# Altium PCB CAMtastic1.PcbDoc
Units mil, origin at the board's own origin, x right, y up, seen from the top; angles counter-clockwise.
Board outline 3395.54 x 1744.22 mil, 2 copper layers (Top Layer, Bottom Layer); 0 components, 61 nets, 284 pads, 0 vias.
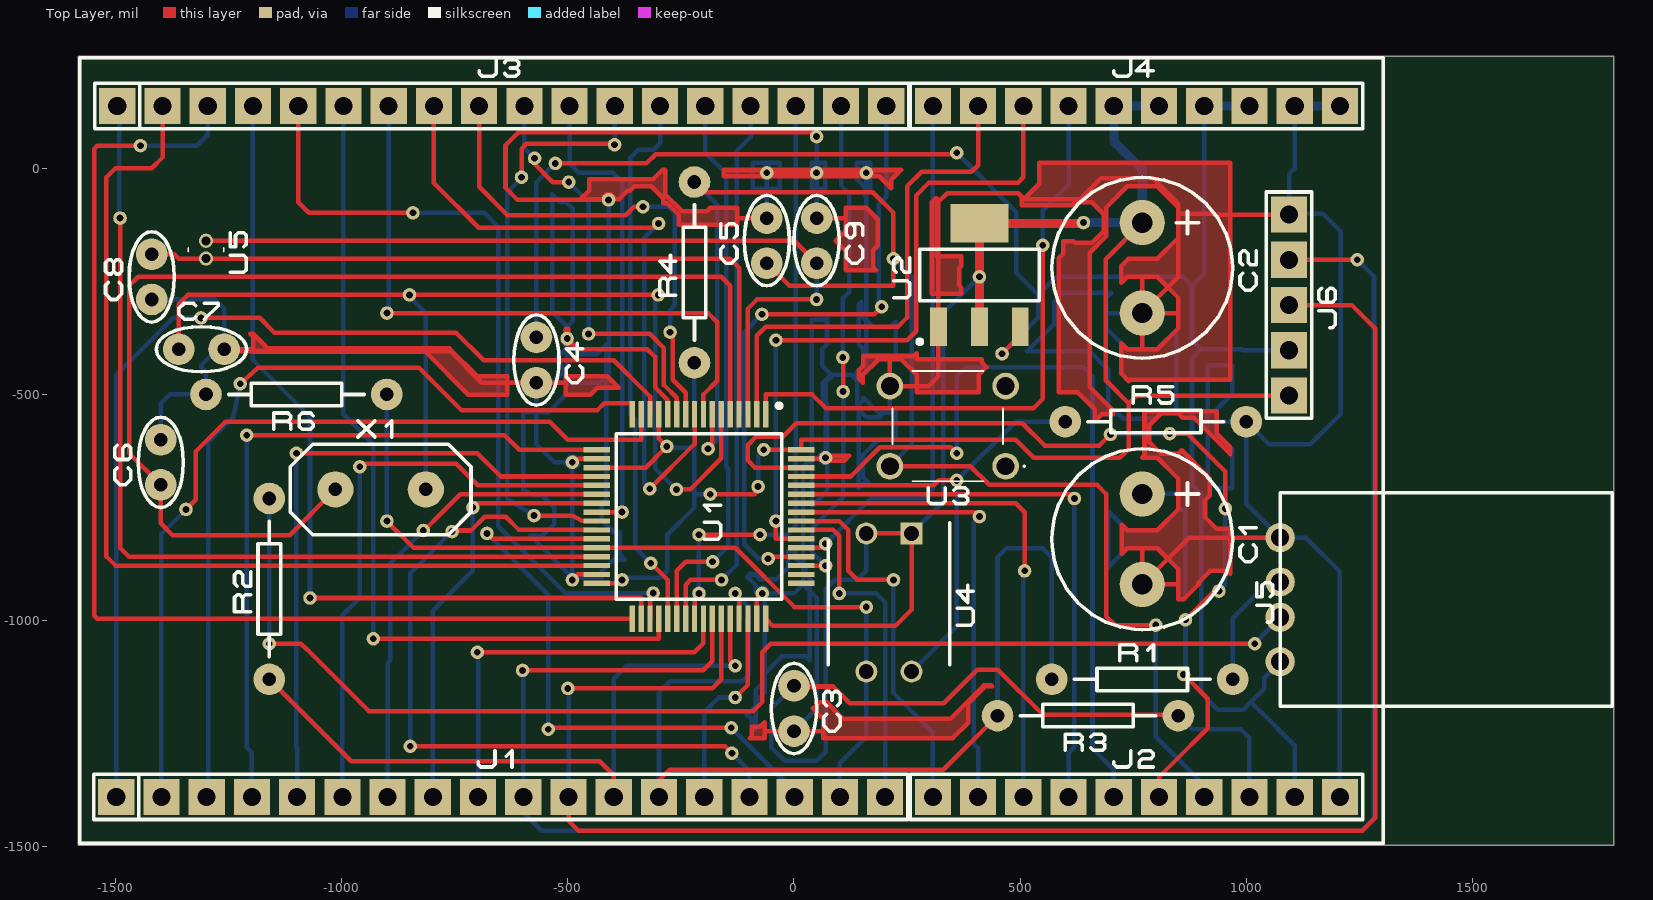
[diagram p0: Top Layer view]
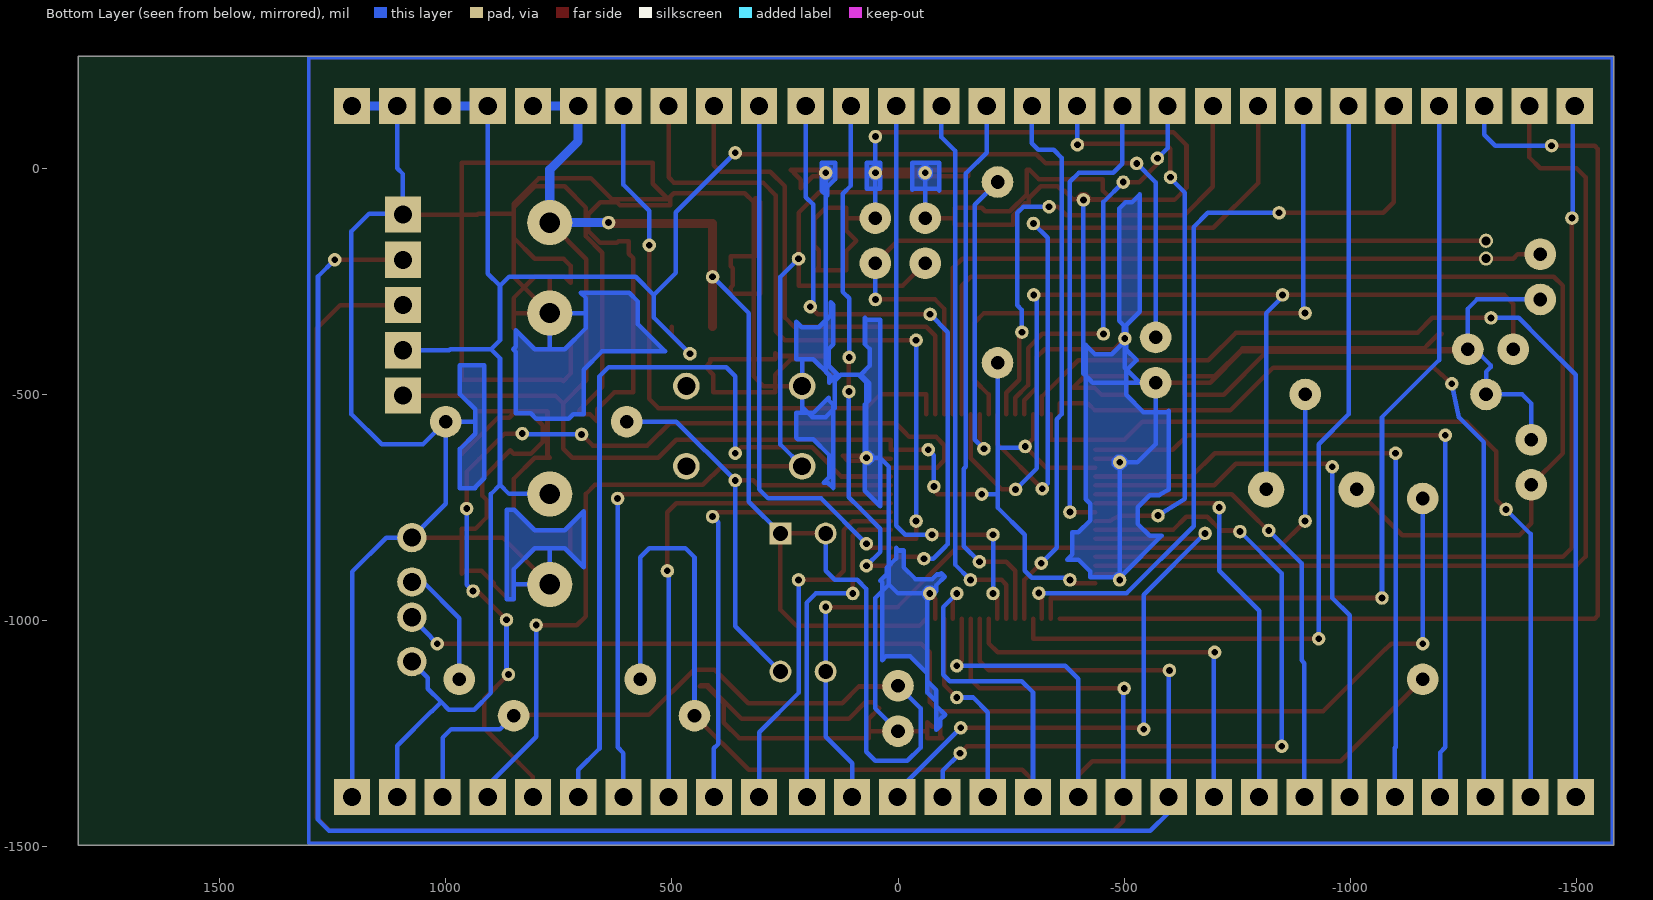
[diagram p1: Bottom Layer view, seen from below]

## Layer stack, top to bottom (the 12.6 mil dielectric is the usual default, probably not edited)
Top Solder: solder mask 0.4, Solder Resist, Dk 3.5
Top Layer: signal copper 1.4
Dielectric 1: dielectric 12.6, FR-4, Dk 4.8
Bottom Layer: signal copper 1.4
Bottom Solder: solder mask 0.4, Solder Resist, Dk 3.5

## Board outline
-1582.74,-1496.13 1812.8,-1496.13 1812.8,248.09 -1582.74,248.09

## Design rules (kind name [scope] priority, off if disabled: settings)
Clearance [All] p1: gap=10 ignorepadtopadclearanceinfootprint=FALSE except(0: Arc-Hole Track-Hole SMDPad-Hole THPad-Hole Via-Hole Fill-Hole Poly-Hole Region-Hole Text-Hole)
PolygonConnect CAM_PolygonConnect_$Net65 [InNet('$Net65')] p1: connectstyle=Direct reliefconductorwidth=10 reliefentries=4 polygonreliefangle="90 Angle" airgapwidth=10
PolygonConnect [All] p2: connectstyle=Relief reliefconductorwidth=10 reliefentries=4 polygonreliefangle="90 Angle" airgapwidth=10
RoutingVias [All] p1: holewidth=28 width=50 viastyle="Through Hole" minholewidth=28 minwidth=50 maxholewidth=28 maxwidth=50
SolderMaskExpansion [All] p1: expansion=4
Width [All] p1: maxlimit=10 minlimit=10 preferedwidth=10
30 further rules are at their usual default settings.

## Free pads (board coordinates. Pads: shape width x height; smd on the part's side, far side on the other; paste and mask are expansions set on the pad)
  rect 80x80 hole 40: 1(-1498.42,-1389.76) 1(-1496.06,137.8) 1(-1398.42,-1389.76) 1(-1396.06,137.8) 1(-1298.42,-1389.76) 1(-1296.06,137.8) 1(-1198.42,-1389.76) 1(-1196.06,137.8) 1(-1098.42,-1389.76) 1(-1096.06,137.8) 1(-998.42,-1389.76) 1(-996.06,137.8) 1(-898.42,-1389.76) 1(-896.06,137.8) 1(-798.42,-1389.76) 1(-796.06,137.8) 1(-698.42,-1389.76) 1(-696.06,137.8) 1(-598.42,-1389.76) 1(-596.06,137.8) 1(-498.42,-1389.76) 1(-496.06,137.8) 1(-398.42,-1389.76) 1(-396.06,137.8) 1(-298.42,-1389.76) 1(-296.06,137.8) 1(-198.42,-1389.76) 1(-196.06,137.8) 1(-98.42,-1389.76) 1(-96.06,137.8) 1(1.58,-1389.76) 1(3.94,137.8) 1(101.58,-1389.76) 1(103.94,137.8) 1(201.58,-1389.76) 1(203.94,137.8) 1(307.09,-1389.76) 1(307.09,137.8) 1(407.09,-1389.76) 1(407.09,137.8) 1(507.09,-1389.76) 1(507.09,137.8) 1(607.09,-1389.76) 1(607.09,137.8) 1(707.09,-1389.76) 1(707.09,137.8) 1(807.09,-1389.76) 1(807.09,137.8) 1(907.09,-1389.76) 1(907.09,137.8) 1(1007.09,-1389.76) 1(1007.09,137.8) 1(1094.49,-502.36) 1(1094.49,-402.36) 1(1094.49,-302.36) 1(1094.49,-202.36) 1(1094.49,-102.36) 1(1107.09,-1389.76) 1(1107.09,137.8) 1(1207.09,-1389.76) 1(1207.09,137.8)
  round 30 hole 15: 1(-1490,-110) 1(-1444.88,50) 1(-1344.21,-754.21) 1(-1311.02,-330.71) 1(-1224.41,-476.38) 1(-1210,-590) 1(-1160,-1051.18) 1(-1100,-630) 1(-1070,-950) 1(-960,-660) 1(-930,-1040) 1(-900,-780) 1(-900,-320) 1(-850,-280) 1(-848.44,-1277.96) 1(-842.52,-98.42) 1(-819.57,-800.76) 1(-755.91,-803.15) 1(-710,-750) 1(-700,-1070) 1(-678.82,-807.13) 1(-602.36,-19.69) 1(-600,-1110) 1(-574.8,-767.72) 1(-573.44,22.14) 1(-543.31,-1240.16) 1(-527.56,10.79) 1(-501.47,-376.47) 1(-500,-1150) 1(-497.9,-30.59) 1(-490,-910) 1(-490,-650) 1(-454.12,-366.12) 1(-410,-70) 1(-396.53,52.07) 1(-380,-910) 1(-380,-760) 1(-334.03,-84.94) 1(-318.9,-708.66) 1(-316.52,-873.02) 1(-311.3,-939.06) 1(-300,-280) 1(-299.21,-122.05) 1(-281.09,-615) 1(-273.89,-362.31) 1(-260,-710) 1(-210,-940) 1(-210,-810) 1(-190,-620) 1(-185.04,-720.47) 1(-180,-870) 1(-160,-910) 1(-138.64,-1237.06) 1(-137.2,-1293.16) 1(-130,-1170) 1(-130,-1100) 1(-130,-940) 1(-79.29,-703.77) 1(-74.8,-810) 1(-70.87,-322.83) 1(-70,-940) 1(-66.93,-622.05) 1(-60,-10) 1(-57.26,-863.06) 1(-40,-780) 1(-40,-380) 1(50,-290) 1(50,-10) 1(50,70) 1(69.95,-878.75) 1(70,-830) 1(70,-640) 1(100,-940) 1(108.03,-418.08) 1(108.68,-493.6) 1(160,-970) 1(160,-10) 1(193.89,-306.21) 1(220,-910) 1(220,-200) 1(359.87,34.19) 1(360,-690) 1(360,-630) 1(410,-770) 1(410,-240) 1(460,-410) 1(510,-890) 1(550,-170) 1(620,-730) 1(640,-120) 1(699.63,-588.44) 1(800,-1010) 1(830.71,-586.61) 1(861.52,-1119.17) 1(865.62,-998.27) 1(939.39,-934.75) 1(953.73,-752.37) 1(1018.82,-1051.18) 1(1245.33,-202.06)
  round 70 hole 30: 1(-1420,-290) 1(-1420,-190) 1(-1400,-700) 1(-1400,-600) 1(-1360,-400) 1(-1300,-500) 1(-1260,-400) 1(-1160,-1130) 1(-1160,-730) 1(-900,-500) 1(-569.37,-473.94) 1(-569.37,-373.94) 1(-220,-430.31) 1(-220,-30.31) 1(-60,-210) 1(-60,-110) 1(0,-1244.25) 1(0,-1144.25) 1(50,-210) 1(50,-110) 1(450,-1210) 1(570,-1130) 1(600,-560) 1(850,-1210) 1(970,-1130) 1(1000,-560)
  round 31.5 hole 20.1: 1(-1300,-199.69) 1(-1300,-160.31)
  round 80 hole 30: 1(-1013.94,-710) 1(-813.94,-710)
  rect 58.27x11.81 smd: 1(-435.98,-917.64) 1(-435.98,-897.95) 1(-435.98,-878.27) 1(-435.98,-858.58) 1(-435.98,-838.9) 1(-435.98,-819.21) 1(-435.98,-799.53) 1(-435.98,-779.84) 1(-435.98,-760.16) 1(-435.98,-740.47) 1(-435.98,-720.79) 1(-435.98,-701.1) 1(-435.98,-681.42) 1(-435.98,-661.73) 1(-435.98,-642.05) 1(-435.98,-622.36) 1(15.98,-917.64) 1(15.98,-897.95) 1(15.98,-878.27) 1(15.98,-858.58) 1(15.98,-838.9) 1(15.98,-819.21) 1(15.98,-799.53) 1(15.98,-779.84) 1(15.98,-760.16) 1(15.98,-740.47) 1(15.98,-720.79) 1(15.98,-701.1) 1(15.98,-681.42) 1(15.98,-661.73) 1(15.98,-642.05) 1(15.98,-622.36)
  rect 11.81x58.27 smd: 1(-357.64,-995.98) 1(-357.64,-544.02) 1(-337.95,-995.98) 1(-337.95,-544.02) 1(-318.27,-995.98) 1(-318.27,-544.02) 1(-298.58,-995.98) 1(-298.58,-544.02) 1(-278.9,-995.98) 1(-278.9,-544.02) 1(-259.21,-995.98) 1(-259.21,-544.02) 1(-239.53,-995.98) 1(-239.53,-544.02) 1(-219.84,-995.98) 1(-219.84,-544.02) 1(-200.16,-995.98) 1(-200.16,-544.02) 1(-180.47,-995.98) 1(-180.47,-544.02) 1(-160.79,-995.98) 1(-160.79,-544.02) 1(-141.1,-995.98) 1(-141.1,-544.02) 1(-121.42,-995.98) 1(-121.42,-544.02) 1(-101.73,-995.98) 1(-101.73,-544.02) 1(-82.05,-995.98) 1(-82.05,-544.02) 1(-62.36,-995.98) 1(-62.36,-544.02)
  round 48.42 hole 32.7: 1(160,-1112.76) 1(160,-807.24) 1(260,-1112.76)
  round 59.05 hole 39.4: 1(212.05,-658.58) 1(212.05,-481.42) 1(467.95,-658.58) 1(467.95,-481.42)
  rect 48.42x48.42 hole 32.7: 1(260,-807.24)
  round 10 smd far side: 1(260,-807.24) 1(1074.8,-1090.55) 1(1074.8,-992.55) 1(1074.8,-914.55) 1(1074.8,-816.55)
  round 10 smd: 1(260,-807.24) 1(1074.8,-1090.55) 1(1074.8,-992.55) 1(1074.8,-914.55) 1(1074.8,-816.55)
  rect 37x85 smd: 1(319.45,-350) 1(410,-350) 1(500.55,-350)
  rect 128x85 smd: 1(410,-121.65)
  round 100 hole 45: 1(770,-920) 1(770,-720) 1(770,-320) 1(770,-120)
  round 65 hole 40: 1(1074.8,-1090.55) 1(1074.8,-992.55) 1(1074.8,-914.55) 1(1074.8,-816.55)

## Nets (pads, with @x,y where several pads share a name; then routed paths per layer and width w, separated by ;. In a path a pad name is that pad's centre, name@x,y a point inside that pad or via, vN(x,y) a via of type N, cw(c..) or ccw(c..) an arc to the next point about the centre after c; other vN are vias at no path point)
$Net0: pad.1@50,-210 pad.1@50,-290 pad.1@-101.73,-544.02 pad.1@-1300,-160.31 | length 1844.6
  Top Layer w10: pad.1@-1300,-160.31 0.32,-160.31 pad.1@50,-210 ; pad.1@-101.73,-544.02 -101.73,-310 -81.73,-290 pad.1@50,-290
  Bottom Layer w10: pad.1@50,-290 pad.1@50,-210
$Net2: pad.1@212.05,-658.58 pad.1@220,-200 pad.1@800,-1010 pad.1@907.09,-1389.76 pad.1@-60,-210 pad.1@-180.47,-544.02 pad.1@-190,-620 pad.1@-220,-30.31 | length 3439.9
  Top Layer w10: pad.1@-220,-30.31 -197.74,-52.58 174.13,-52.58 220,-98.45 220,-200 220,-260 -10,-260 pad.1@-60,-210 ; pad.1@-190,-620 -180.47,-610.47 pad.1@-180.47,-544.02 ; pad.1@212.05,-658.58 390,-658.58 431.42,-700 670,-700 690,-720 690,-990 710,-1010 pad.1@800,-1010
  Bottom Layer w10: pad.1@-220,-30.31 -170,-80.31 -170,-600 pad.1@-190,-620 ; pad.1@212.05,-658.58 260,-610.63 260,-240 pad.1@220,-200 ; pad.1@800,-1010 800,-1256.69 907.09,-1363.78 pad.1@907.09,-1389.76
$Net3: pad.1@-200.16,-544.02 pad.1@-896.06,137.8 pad.1@-900,-320 | length 1414.2
  Top Layer w10: pad.1@-900,-320 -190,-320 -170,-340 -170,-469.84 -200.16,-500 pad.1@-200.16,-544.02
  Bottom Layer w10: pad.1@-900,-320 -896.06,-316.06 pad.1@-896.06,137.8
$Net4: pad.1@0,-1144.25 pad.1@15.98,-622.36 pad.1@160,-807.24 pad.1@260,-807.24 pad.1@410,-121.65 pad.1@410,-240 pad.1@410,-350 pad.1@640,-120 pad.1@707.09,137.8 pad.1@770,-120 pad.1@807.09,137.8 pad.1@850,-1210 pad.1@1007.09,-1389.76 pad.1@1094.49,-502.36 pad.1@-62.36,-995.98 pad.1@-66.93,-622.05 pad.1@-79.29,-703.77 pad.1@-185.04,-720.47 pad.1@-220,-430.31 pad.1@-281.09,-615 pad.1@-298.58,-544.02 pad.1@-380,-910 pad.1@-435.98,-661.73 pad.1@-435.98,-917.64 | length 7338.7
  Top Layer w10: pad.1@-435.98,-917.64 -387.64,-917.64 pad.1@-380,-910 ; pad.1@-435.98,-661.73 -327.82,-661.73 -281.09,-615 -298.58,-597.5 ; pad.1@-185.04,-720.47 -86.61,-720.47 pad.1@-79.29,-703.77 ; pad.1@-66.93,-622.05 15.67,-622.05 15.98,-622.36 15.98,-600 490,-600 530,-640 720,-640 740,-620 740,-520 ; pad.1@-62.36,-995.98 -46.54,-1011.81 224.17,-1011.81 260,-975.98 260,-807.24 200,-807.24 pad.1@160,-807.24 ; pad.1@0,-1144.25 1.42,-1145.67 86.61,-1145.67 123.37,-1182.42 331.16,-1182.42 405.23,-1108.35 450.87,-1108.35 551.18,-1208.66 850,-1208.66 pad.1@850,-1210 ; pad.1@770,-120 688.98,-201.02 688.98,-468.98 740,-520 ; pad.1@1094.49,-502.36 757.64,-502.36 740,-520 ; -298.58,-597.5 -298.58,-573.15 ; -298.58,-597.5 -298.58,-573.15 ; -298.58,-573.15 -298.58,-544.02 -298.58,-573.15
  Top Layer w20: pad.1@410,-350 410,-280 410,-240 410,-121.65 638.35,-121.65 pad.1@640,-120
  Bottom Layer w10: pad.1@-380,-910 -375.51,-905.51 -295.51,-905.51 -280,-890 -280,-810 -220,-750 -220,-720.47 ; pad.1@-281.09,-615 -277.98,-618.11 -220,-618.11 ; pad.1@-220,-430.31 -220,-573.08 -220,-618.11 ; pad.1@-185.04,-720.47 -220,-720.47 ; pad.1@-79.29,-703.77 -79.29,-634.41 pad.1@-66.93,-622.05 ; pad.1@0,-1144.25 -50,-1194.25 -50,-1280.71 -20.71,-1310 50,-1310 70,-1290 70,-930 90,-910 140,-910 160,-890 pad.1@160,-807.24 ; pad.1@260,-807.24 330,-737.24 330,-320 pad.1@410,-240 ; pad.1@850,-1210 880.16,-1240.16 988.19,-1240.16 1007.09,-1259.06 pad.1@1007.09,-1389.76 ; -220,-720.47 -220,-618.11
  Bottom Layer w20: pad.1@640,-120 770,-120 770,-2.91 707.09,60 707.09,137.8 pad.1@807.09,137.8
$Net5: pad.1@-435.98,-622.36 pad.1@-1198.42,-1389.76 pad.1@-1210,-590 | length 1592
  Top Layer w10: pad.1@-1210,-590 -640,-590 -607.64,-622.36 pad.1@-435.98,-622.36
  Bottom Layer w10: pad.1@-1210,-590 -1210,-1280 -1198.42,-1291.58 pad.1@-1198.42,-1389.76
$Net6: pad.1@-435.98,-681.42 pad.1@-1098.42,-1389.76 pad.1@-1100,-630 | length 1445.7
  Top Layer w10: pad.1@-1100,-630 -700,-630 -648.58,-681.42 pad.1@-435.98,-681.42
  Bottom Layer w10: pad.1@-1100,-630 -1100,-1280 -1098.42,-1281.58 pad.1@-1098.42,-1389.76
$Net7: pad.1@-435.98,-740.47 pad.1@-710,-750 pad.1@-798.42,-1389.76 | length 954.4
  Top Layer w10: pad.1@-710,-750 -700.47,-740.47 pad.1@-435.98,-740.47
  Bottom Layer w10: pad.1@-798.42,-1389.76 -798.42,-978.42 -710,-890 pad.1@-710,-750
$Net8: pad.1@-380,-760 pad.1@-435.98,-760.16 pad.1@-496.06,137.8 | length 1046.5
  Top Layer w10: pad.1@-435.98,-760.16 -380.16,-760.16 pad.1@-380,-760
  Bottom Layer w10: pad.1@-496.06,137.8 -496.06,10 -476.06,-10 -400,-10 -380,-30 pad.1@-380,-760
$Net9: pad.1@101.58,-1389.76 pad.1@160,-970 pad.1@160,-1112.76 pad.1@-435.98,-838.9 pad.1@-900,-500 pad.1@-900,-780 | length 1863.3
  Top Layer w10: pad.1@-900,-780 -841.1,-838.9 -435.98,-838.9 -130,-838.9 1.1,-970 pad.1@160,-970 ; pad.1@101.12,-1389.31 pad.1@101.58,-1389.76
  Bottom Layer w10: pad.1@-900,-780 pad.1@-900,-500 ; pad.1@101.58,-1389.76 101.58,-1315.38 144.49,-1272.47 160,-1256.95 160,-1112.76 pad.1@160,-970
$Net10: pad.1@-130,-1100 pad.1@-141.1,-995.98 pad.1@-398.42,-1389.76 pad.1@-1160,-1130 | length 1547.5
  Top Layer w10: pad.1@-1160,-1130 -978.98,-1311.02 -429.13,-1311.02 -398.42,-1341.73 pad.1@-398.42,-1389.76 ; pad.1@-141.1,-995.98 -141.1,-1088.9 pad.1@-130,-1100
  Bottom Layer w10: pad.1@-398.42,-1389.76 -398.42,-1128.42 -370,-1100 pad.1@-130,-1100
$Net11: pad.1@1094.49,-302.36 pad.1@-160.79,-995.98 pad.1@-498.42,-1389.76 pad.1@-500,-1150 | length 3872.4
  Top Layer w10: pad.1@-500,-1150 -180.79,-1150 -160.79,-1130 pad.1@-160.79,-995.98 ; pad.1@-498.44,-1389.78 -498.44,-1442.43 -476.3,-1464.57 1255.91,-1464.57 1284.68,-1435.8 1284.68,-353.67 1233.36,-302.36 pad.1@1094.49,-302.36
  Bottom Layer w10: pad.1@-500,-1150 -498.42,-1151.58 pad.1@-498.42,-1389.76
$Net12: pad.1@1094.49,-202.36 pad.1@1245.33,-202.06 pad.1@-180.47,-995.98 pad.1@-598.42,-1389.76 pad.1@-600,-1110 | length 4149.1
  Top Layer w10: pad.1@-600,-1110 -200.47,-1110 -180.47,-1090 pad.1@-180.47,-995.98 ; pad.1@1094.49,-202.36 1094.8,-202.06 pad.1@1245.33,-202.06
  Bottom Layer w10: pad.1@-600,-1110 -598.42,-1111.58 -598.42,-1389.76 -598.42,-1424.28 -557.92,-1464.79 1258.06,-1464.79 1282.36,-1440.48 1282.36,-239.09 pad.1@1245.33,-202.06
$Net13: pad.1@-200.16,-995.98 pad.1@-698.42,-1389.76 pad.1@-700,-1070 | length 882.6
  Top Layer w10: pad.1@-700,-1070 -220.16,-1070 -200.16,-1050 pad.1@-200.16,-995.98
  Bottom Layer w10: pad.1@-700,-1070 -698.42,-1071.58 pad.1@-698.42,-1389.76
$Net14: pad.1@-298.58,-995.98 pad.1@-930,-1040 pad.1@-996.06,137.8 | length 1880.6
  Top Layer w10: pad.1@-930,-1040 -298.58,-1040 pad.1@-298.58,-995.98
  Bottom Layer w10: pad.1@-996.06,137.8 -996.06,-543.94 -930,-610 pad.1@-930,-1040
$Net15: pad.1@-337.95,-995.98 pad.1@-1070,-950 pad.1@-1196.06,137.8 | length 1918
  Top Layer w10: pad.1@-1070,-950 -337.95,-950 pad.1@-337.95,-995.98
  Bottom Layer w10: pad.1@-1196.06,137.8 -1196.06,-423.94 -1070,-550 pad.1@-1070,-950
$Net16: pad.1@15.98,-681.42 pad.1@360,-630 pad.1@707.09,-1389.76 | length 1811.9
  Top Layer w10: pad.1@15.98,-681.42 125.61,-681.42 190,-617.03 347.03,-617.03 pad.1@360,-630
  Bottom Layer w10: pad.1@360,-630 360,-460 380,-440 640,-440 660,-460 660,-1282.91 707.09,-1330 pad.1@707.09,-1389.76
$Net17: pad.1@15.98,-701.1 pad.1@260,-1112.76 pad.1@360,-690 pad.1@600,-560 | length 1106.6
  Top Layer w10: pad.1@15.98,-701.1 308.9,-701.1 320,-690 pad.1@360,-690
  Bottom Layer w10: pad.1@260,-1112.76 360,-1012.76 360,-690 490,-560 pad.1@600,-560
$Net18: pad.1@15.98,-720.79 pad.1@607.09,-1389.76 pad.1@620,-730 | length 1272.9
  Top Layer w10: pad.1@15.98,-720.79 610.79,-720.79 pad.1@620,-730
  Bottom Layer w10: pad.1@607.09,-1389.76 607.09,-1292.91 620,-1280 pad.1@620,-730
$Net19: pad.1@15.98,-740.47 pad.1@507.09,-1389.76 pad.1@510,-890 | length 1132.8
  Top Layer w10: pad.1@15.98,-740.47 490,-740.47 510,-760.47 pad.1@510,-890
  Bottom Layer w10: pad.1@507.09,-1389.76 507.09,-892.91 pad.1@510,-890
$Net20: pad.1@15.98,-779.84 pad.1@220,-910 pad.1@307.09,-1389.76 | length 826.6
  Top Layer w10: pad.1@15.98,-779.84 100,-779.84 120,-799.84 120,-890 140,-910 pad.1@220,-910
  Bottom Layer w10: pad.1@220,-910 220,-1160 307.09,-1247.09 pad.1@307.09,-1389.76
$Net21: pad.1@15.98,-838.9 pad.1@70,-830 pad.1@307.09,137.8 | length 1192.3
  Top Layer w10: pad.1@15.98,-838.9 61.1,-838.9 pad.1@70,-830
  Bottom Layer w10: pad.1@70,-830 170,-730 287.09,-730 307.09,-710 pad.1@307.09,137.8
$Net24: pad.1@15.98,-760.16 pad.1@407.09,-1389.76 pad.1@410,-770 | length 1026.9
  Top Layer w10: pad.1@15.98,-760.16 400.16,-760.16 pad.1@410,-770
  Bottom Layer w10: pad.1@407.09,-1389.76 407.09,-1282.09 397.64,-1272.64 397.64,-782.36 pad.1@410,-770
$Net25: pad.1@-435.98,-701.1 pad.1@-960,-660 pad.1@-998.42,-1389.76 | length 1292.1
  Top Layer w10: pad.1@-960,-660 -953.54,-653.54 -746.46,-653.54 -698.9,-701.1 pad.1@-435.98,-701.1
  Bottom Layer w10: pad.1@-998.42,-1389.76 -998.42,-988.42 -960,-950 pad.1@-960,-660
$Net26: pad.1@15.98,-661.73 pad.1@699.63,-588.44 pad.1@807.09,-1389.76 pad.1@830.71,-586.61 pad.1@861.52,-1119.17 pad.1@865.62,-998.27 pad.1@939.39,-934.75 pad.1@953.73,-752.37 | length 2131.2
  Top Layer w10: pad.1@15.98,-661.73 -86.3,-661.73 -102.36,-645.67 -102.36,-612.19 -84.13,-593.96 -25.14,-593.96 -12.44,-581.26 5.4,-563.41 504.52,-563.41 554.14,-613.03 675.04,-613.03 pad.1@699.63,-588.44 ; pad.1@807.09,-1389.76 807.09,-1345.74 838.98,-1313.85 914.8,-1238.03 914.8,-1172.45 pad.1@861.52,-1119.17 ; pad.1@830.71,-586.61 869.94,-586.61 927.09,-643.76 953.73,-670.4 pad.1@953.73,-752.37 ; pad.1@865.62,-998.27 929.14,-934.75 pad.1@939.39,-934.75
  Bottom Layer w10: pad.1@699.63,-588.44 828.88,-588.44 pad.1@830.71,-586.61 ; pad.1@861.52,-1119.17 865.62,-1115.08 pad.1@865.62,-998.27 ; pad.1@939.39,-934.75 953.73,-920.4 pad.1@953.73,-752.37
$Net27: pad.1@-180,-870 pad.1@-196.06,137.8 pad.1@-259.21,-995.98 | length 1236.4
  Top Layer w10: pad.1@-259.21,-995.98 -259.21,-890 -239.21,-870 pad.1@-180,-870
  Bottom Layer w10: pad.1@-196.06,137.8 -196.06,34.65 -150,-11.42 -150,-660 -145.67,-664.33 -145.67,-835.67 pad.1@-180,-870
$Net29: pad.1@-259.21,-544.02 pad.1@-454.12,-366.12 pad.1@-497.9,-30.59 pad.1@-573.44,22.14 pad.1@-596.06,137.8 | length 924.4
  Top Layer w10: pad.1@-573.44,22.14 -575.74,22.14 -575.74,12.1 -533.06,-30.59 pad.1@-497.9,-30.59 ; pad.1@-454.12,-366.12 -318.92,-366.12 -287.4,-397.64 -287.4,-479.16 -259.21,-507.35 pad.1@-259.21,-544.02
  Bottom Layer w10: pad.1@-596.06,137.8 -596.06,44.76 pad.1@-573.44,22.14 ; pad.1@-497.9,-30.59 -454.12,-74.37 pad.1@-454.12,-366.12
$Net30: pad.1@359.87,34.19 pad.1@460,-410 pad.1@500.55,-350 pad.1@770,-720 pad.1@907.09,137.8 pad.1@1007.09,137.8 pad.1@1074.8,-1090.55 pad.1@1094.49,-402.36 pad.1@1107.09,-1389.76 pad.1@-527.56,10.79 pad.1@-569.37,-373.94 | length 4539.3
  Top Layer w10: pad.1@-527.56,10.79 -326.1,10.79 -305.66,31.23 356.91,31.23 pad.1@359.87,34.19 ; pad.1@460,-410 500.55,-369.45 pad.1@500.55,-350
  Bottom Layer w10: pad.1@-569.37,-373.94 -569.37,-31.02 pad.1@-527.56,10.79 ; pad.1@359.87,34.19 491.45,-97.39 491.45,-231.45 540,-280 ; pad.1@460,-410 540,-330 540,-280 ; pad.1@770,-720 860,-720 880,-700 ; pad.1@907.09,137.8 907.09,-232.91 880,-260 ; pad.1@1074.8,-1090.55 1039.37,-1125.98 1039.37,-1150.63 1010,-1180 ; pad.1@1094.49,-402.36 992.36,-402.36 990,-400 900,-400 ; pad.1@1107.09,-1389.76 1107.09,-1276.38 1030.71,-1200 1030,-1200 1010,-1180 ; 540,-280 580,-240 860,-240 880,-260 ; 880,-700 900,-720 900,-1160 936.85,-1196.85 993.15,-1196.85 1010,-1180 ; 880,-700 880,-420 900,-400 ; 880,-260 880,-380 900,-400
  Bottom Layer w20: pad.1@907.09,137.8 pad.1@1007.09,137.8
$Net31: pad.1@-311.3,-939.06 pad.1@-318.27,-995.98 pad.1@-842.52,-98.42 pad.1@-1096.06,137.8 | length 1802.7
  Top Layer w10: pad.1@-1096.06,137.8 -1095.61,137.34 -1095.61,-75.33 -1072.52,-98.42 pad.1@-842.52,-98.42 ; pad.1@-318.27,-995.98 -318.27,-946.03 pad.1@-311.3,-939.06
  Bottom Layer w10: pad.1@-842.52,-98.42 -685.04,-98.42 -653.54,-129.92 -653.54,-791.34 -505.82,-939.06 pad.1@-311.3,-939.06
$Net32: pad.1@-435.98,-720.79 pad.1@-819.57,-800.76 pad.1@-898.42,-1389.76 | length 1038.4
  Top Layer w10: pad.1@-819.57,-800.76 -818.05,-800.76 -778.53,-761.25 -738.08,-720.79 pad.1@-435.98,-720.79
  Bottom Layer w10: pad.1@-898.42,-1389.76 -898.42,-1093.9 -892.52,-1087.99 -892.52,-873.71 pad.1@-819.57,-800.76
$Net33: pad.1@15.98,-858.58 pad.1@193.89,-306.21 pad.1@203.94,137.8 pad.1@-57.26,-863.06 pad.1@-70.87,-322.83 | length 1390.6
  Top Layer w10: pad.1@-70.87,-322.83 177.27,-322.83 pad.1@193.89,-306.21 ; pad.1@-57.26,-863.06 -52.79,-858.58 pad.1@15.98,-858.58
  Bottom Layer w10: pad.1@-70.87,-322.83 -110.24,-362.2 -110.24,-767.72 -110.24,-830.71 -102.36,-838.58 -77.89,-863.06 pad.1@-57.26,-863.06 ; pad.1@193.89,-306.21 187.72,-300.04 187.72,-222.88 187.72,-80 203.94,-63.78 pad.1@203.94,137.8
$Net34: pad.1@-219.84,-544.02 pad.1@-299.21,-122.05 pad.1@-318.9,-708.66 pad.1@-796.06,137.8 | length 1522.4
  Top Layer w10: pad.1@-796.06,137.8 -796.06,-32.5 -696.92,-131.64 -308.81,-131.64 pad.1@-299.21,-122.05 ; pad.1@-318.9,-708.66 -219.84,-609.61 pad.1@-219.84,-544.02
  Bottom Layer w10: pad.1@-318.9,-708.66 -330.71,-696.85 -330.71,-153.54 pad.1@-299.21,-122.05
$Net35: pad.1@-239.53,-544.02 pad.1@-273.89,-362.31 pad.1@-334.03,-84.94 pad.1@-696.06,137.8 | length 1114.3
  Top Layer w10: pad.1@-696.06,137.8 -695.97,137.7 -695.97,-41.09 -633.47,-103.59 -372.28,-103.59 -353.62,-84.94 pad.1@-334.03,-84.94 ; pad.1@-273.89,-362.31 -267.72,-368.48 -267.72,-467.78 -239.53,-495.97 pad.1@-239.53,-544.02
  Bottom Layer w10: pad.1@-334.03,-84.94 -277.27,-84.94 -263.78,-98.43 -263.78,-303.15 -273.89,-313.26 pad.1@-273.89,-362.31
$Net36: pad.1@-396.06,137.8 pad.1@-396.53,52.07 pad.1@-435.98,-779.84 pad.1@-574.8,-767.72 pad.1@-602.36,-19.69 | length 1295.6
  Top Layer w10: pad.1@-602.36,-19.69 -602.36,43.38 -591.76,53.98 -398.43,53.98 pad.1@-396.53,52.07 ; pad.1@-574.8,-767.72 -490,-767.72 -468.5,-779.53 pad.1@-435.98,-779.84
  Bottom Layer w10: pad.1@-602.36,-19.69 -602.36,-22.09 -633.86,-53.59 -633.86,-730.71 pad.1@-574.8,-767.72 ; pad.1@-396.53,52.07 -396.53,137.33 pad.1@-396.06,137.8
$Net37: pad.1@15.98,-819.21 pad.1@507.09,137.8 pad.1@-40,-380 pad.1@-40,-780 | length 1524.9
  Top Layer w10: pad.1@-40,-780 -40,-819.21 pad.1@15.98,-819.21 ; pad.1@-40,-380 250,-380 270,-360 270,-60 298.5,-31.5 495.59,-31.5 507.09,-20 pad.1@507.09,137.8
  Bottom Layer w10: pad.1@-40,-780 pad.1@-40,-380
$Net39: pad.1@550,-170 pad.1@607.09,137.8 pad.1@-62.36,-544.02 | length 1348.5
  Top Layer w10: pad.1@-62.36,-544.02 -62.36,-500 40,-500 70,-530 530,-530 550,-510 pad.1@550,-170
  Bottom Layer w10: pad.1@550,-170 550,-93.6 607.09,-36.51 pad.1@607.09,137.8
$Net40: pad.1@-98.42,-1389.76 pad.1@-137.2,-1293.16 pad.1@-435.98,-799.53 pad.1@-755.91,-803.15 pad.1@-848.44,-1277.96 | length 1688.9
  Top Layer w10: pad.1@-848.44,-1277.96 -152.39,-1277.96 pad.1@-137.2,-1293.16 ; pad.1@-755.91,-803.15 -753.51,-800.76 -714.14,-800.76 -683.75,-770.36 -637.2,-770.36 -608.03,-799.53 pad.1@-435.98,-799.53
  Bottom Layer w10: pad.1@-848.44,-1277.96 -848.44,-895.69 pad.1@-755.91,-803.15 ; pad.1@-137.2,-1293.16 -98.42,-1331.93 pad.1@-98.42,-1389.76
$Net41: pad.1@-357.64,-995.98 pad.1@-1296.06,137.8 pad.1@-1444.88,50 | length 2552
  Top Layer w10: pad.1@-1444.88,50 -1540,50 -1547.24,42.76 -1547.24,-988.74 -1540,-995.98 pad.1@-357.64,-995.98
  Bottom Layer w10: pad.1@-1444.88,50 -1320.08,50 -1296.06,74.02 pad.1@-1296.06,137.8
$Net42: pad.1@-435.98,-858.58 pad.1@-1490,-110 pad.1@-1496.06,137.8 | length 2054.1
  Top Layer w10: pad.1@-1490,-110 -1490,-838.58 -1470,-858.58 pad.1@-435.98,-858.58
  Bottom Layer w10: pad.1@-1496.06,137.8 -1492.13,137.8 -1492.13,-114.66 -1490,-114.66 pad.1@-1490,-110
$Net43: pad.1@-160.79,-544.02 pad.1@-260,-710 pad.1@-300,-280 pad.1@-813.94,-710 pad.1@-850,-280 pad.1@-1360,-400 | length 2296.1
  Top Layer w10: pad.1@-1360,-400 -1360,-300 -1340,-280 -850,-280 pad.1@-300,-280 ; pad.1@-260,-710 -229.68,-710 -160.79,-641.1 pad.1@-160.79,-544.02
  Bottom Layer w10: pad.1@-850,-280 -853.94,-280 -813.94,-320 pad.1@-813.94,-710 ; pad.1@-300,-280 -307.09,-287.09 -307.09,-662.91 pad.1@-260,-710
$Net44: pad.1@3.94,137.8 pad.1@-74.8,-810 pad.1@-210,-810 pad.1@-210,-940 pad.1@-219.84,-995.98 | length 1340.1
  Top Layer w10: pad.1@-219.84,-995.98 -219.84,-949.84 pad.1@-210,-940 ; pad.1@-210,-810 pad.1@-74.8,-810
  Bottom Layer w10: pad.1@-210,-940 pad.1@-210,-810 ; pad.1@-74.8,-810 -16.06,-810 3.94,-790 pad.1@3.94,137.8
$Net45: pad.1@-278.9,-995.98 pad.1@-296.06,137.8 pad.1@-316.52,-873.02 | length 1223
  Top Layer w10: pad.1@-316.52,-873.02 -315.96,-873.02 -278.9,-910.08 pad.1@-278.9,-995.98
  Bottom Layer w10: pad.1@-316.52,-873.02 -350.65,-838.89 -350.65,-554.87 -362.2,-543.31 -362.2,22.9 -344.41,40.7 -309.69,40.7 -295.28,55.12 -295.28,140.12 -294.7,140.7 pad.1@-296.06,137.8
$Net47: pad.1@-318.27,-544.02 pad.1@-1311.02,-330.71 pad.1@-1498.42,-1389.76 | length 2276.9
  Top Layer w10: pad.1@-1311.02,-330.71 -1181.1,-330.71 -1148.53,-363.28 -747.06,-363.28 -685.91,-424.44 -613.4,-424.44 -398.27,-424.44 -329.34,-493.37 -318.27,-504.44 pad.1@-318.27,-544.02
  Bottom Layer w10: pad.1@-1498.42,-1389.76 -1498.42,-456.82 -1421.25,-379.64 -1372.32,-330.71 pad.1@-1311.02,-330.71
$Net48: pad.1@-101.73,-995.98 pad.1@-130,-1170 pad.1@-198.42,-1389.76 | length 455
  Top Layer w10: pad.1@-130,-1170 -101.73,-1141.73 pad.1@-101.73,-995.98
  Bottom Layer w10: pad.1@-198.42,-1389.76 -198.42,-1202.36 -166.06,-1170 pad.1@-130,-1170
$Net49: pad.1@1018.82,-1051.18 pad.1@1074.8,-992.55 pad.1@-1160,-730 pad.1@-1160,-1051.18 | length 2768.3
  Top Layer w10: pad.1@-1160,-1051.18 -1090.55,-1051.18 -1070,-1070 -940,-1200 -90,-1200 -70,-1180 -70,-1070 -51.18,-1051.18 pad.1@1018.82,-1051.18
  Bottom Layer w10: pad.1@-1160,-1051.18 pad.1@-1160,-730 ; pad.1@1018.82,-1051.18 pad.1@1074.8,-992.55
$Net50: pad.1@15.98,-799.53 pad.1@100,-940 pad.1@201.58,-1389.76 | length 756.5
  Top Layer w10: pad.1@15.98,-799.53 86.93,-799.53 100,-812.6 pad.1@100,-940
  Bottom Layer w10: pad.1@100,-940 181.58,-940 201.58,-960 pad.1@201.58,-1389.76
$Net51: pad.1@-337.95,-544.02 pad.1@-1344.21,-754.21 pad.1@-1398.42,-1389.76 | length 1879.9
  Top Layer w10: pad.1@-1344.21,-754.21 -1322.84,-732.84 -1322.84,-625.98 -1256.85,-560 -540,-560 -500,-600 -337.95,-600 pad.1@-337.95,-544.02
  Bottom Layer w10: pad.1@-1398.42,-1389.76 -1398.42,-808.42 pad.1@-1344.21,-754.21
$Net52: pad.1@-357.64,-544.02 pad.1@-1224.41,-476.38 pad.1@-1298.42,-1389.76 | length 1889.6
  Top Layer w10: pad.1@-1224.41,-476.38 -1185.04,-440.94 -829.06,-440.94 -734.57,-535.43 -435.43,-535.43 -419.68,-519.68 -357.64,-519.68 pad.1@-357.64,-544.02
  Bottom Layer w10: pad.1@-1298.42,-1389.76 -1295.28,-1386.61 -1295.28,-605.28 -1240,-550 pad.1@-1224.41,-476.38
$Net53: pad.1@15.98,-878.27 pad.1@69.95,-878.75 pad.1@103.94,137.8 pad.1@108.03,-418.08 pad.1@108.68,-493.6 | length 1125.6
  Top Layer w10: pad.1@15.98,-878.27 69.46,-878.27 pad.1@69.95,-878.75 ; pad.1@108.03,-418.08 108.68,-418.73 pad.1@108.68,-493.6
  Bottom Layer w10: pad.1@69.95,-878.75 39.41,-848.21 39.41,-816.38 39.41,-796.57 85.13,-750.86 108.68,-727.3 pad.1@108.68,-493.6 ; pad.1@103.94,137.8 104.12,137.61 104.12,-38.18 122.05,-56.11 122.05,-248.03 122.05,-273.45 108.03,-287.46 pad.1@108.03,-418.08
$Net54: pad.1@1.58,-1389.76 pad.1@-138.64,-1237.06 pad.1@-435.98,-819.21 pad.1@-543.31,-1240.16 pad.1@-678.82,-807.13 | length 1378.2
  Top Layer w10: pad.1@-678.82,-807.13 -666.73,-819.21 pad.1@-435.98,-819.21 ; pad.1@-138.64,-1237.06 -542.45,-1236.42 pad.1@-543.31,-1240.16 ; pad.1@-543.31,-1240.16 -541.84,-1233.75 -543.31,-1236.22 pad.1@-543.31,-1240.16
  Bottom Layer w10: pad.1@-678.82,-807.13 -543.31,-942.63 pad.1@-543.31,-1240.16 ; pad.1@-138.64,-1237.06 -141.95,-1233.75 1.58,-1377.28 pad.1@1.58,-1389.76
$Net55: pad.1@-96.06,137.8 pad.1@-160,-910 pad.1@-239.53,-995.98 | length 1233.6
  Top Layer w10: pad.1@-239.53,-995.98 -239.53,-920.63 -228.9,-910 pad.1@-160,-910
  Bottom Layer w10: pad.1@-160,-910 -125.98,-875.98 -125.98,39.02 -96.06,68.94 pad.1@-96.06,137.8
$Net58: pad.1@-435.98,-878.27 pad.1@-1396.06,137.8 | length 2186.6
  Top Layer w10: pad.1@-1396.06,137.8 -1396.06,23.94 -1420,0 -1500,0 -1520,-20 -1520,-858.27 -1500,-878.27 pad.1@-435.98,-878.27
$Net59: pad.1@407.09,137.8 pad.1@-82.05,-544.02 | length 1119.9
  Top Layer w10: pad.1@-82.05,-544.02 -82.05,-370 -62.05,-350 230,-350 250,-330 250,-40 282.13,-7.87 392.13,-7.87 407.09,7.09 pad.1@407.09,137.8
$Net60: pad.1@970,-1130 pad.1@1074.8,-914.55 | length 273.4
  Bottom Layer w10: pad.1@970,-1130 970,-994.57 1050.02,-914.55 pad.1@1074.8,-914.55
$Net61: pad.1@467.95,-658.58
$Net62: pad.1@467.95,-481.42
$Net63: pad.1@-141.1,-544.02 pad.1@-1013.94,-710 pad.1@-1400,-700 | length 2622.2
  Top Layer w10: pad.1@-1013.94,-710 -1114.96,-811.02 -1374.02,-811.02 -1400,-785.04 -1400,-700 -1470,-630 -1470,-260 -1450,-240 -161.1,-240 -141.1,-260 pad.1@-141.1,-544.02
$Net64: pad.1@450,-1210 pad.1@570,-1130 pad.1@-121.42,-995.98 pad.1@-130,-940 pad.1@-298.42,-1389.76 | length 2298.1
  Top Layer w10: pad.1@-298.42,-1389.76 -298.42,-1353.54 -274.88,-1330 330,-1330 pad.1@450,-1210 ; pad.1@-130,-940 -121.42,-948.58 pad.1@-121.42,-995.98
  Bottom Layer w10: pad.1@-298.42,-1389.76 -298.42,-1158.42 -273.86,-1133.86 -114.17,-1133.86 -100,-1119.68 -100,-970 pad.1@-130,-940 ; pad.1@450,-1210 450,-860 470,-840 550,-840 570,-860 pad.1@570,-1130
$Net65: pad.1@0,-1244.25 pad.1@15.98,-642.05 pad.1@50,70 pad.1@50,-10 pad.1@50,-110 pad.1@70,-640 pad.1@160,-10 pad.1@212.05,-481.42 pad.1@319.45,-350 pad.1@770,-320 pad.1@770,-920 pad.1@1000,-560 pad.1@1074.8,-816.55 pad.1@1094.49,-102.36 pad.1@1107.09,137.8 pad.1@1207.09,137.8 pad.1@1207.09,-1389.76 pad.1@-60,-10 pad.1@-60,-110 pad.1@-70,-940 pad.1@-82.05,-995.98 pad.1@-278.9,-544.02 pad.1@-410,-70 pad.1@-435.98,-642.05 pad.1@-435.98,-897.95 pad.1@-490,-650 pad.1@-490,-910 pad.1@-501.47,-376.47 pad.1@-569.37,-473.94 pad.1@-1260,-400 pad.1@-1300,-500 pad.1@-1400,-600 pad.1@-1420,-290 | length 32613
  Top Layer w10: -1195,-400 -1260,-400 -1260,-403.94 -760,-403.94 -690,-473.94 pad.1@-569.37,-473.94 ; -634.37,-473.94 pad.1@-569.37,-473.94 ; -504.37,-473.94 pad.1@-569.37,-473.94 ; pad.1@-501.47,-376.47 -478.22,-399.72 -324.47,-399.72 -307.09,-417.11 -307.09,-484.25 -278.9,-512.44 pad.1@-278.9,-544.02 ; pad.1@-490,-910 -477.95,-897.95 pad.1@-435.98,-897.95 ; pad.1@-490,-650 -482.05,-642.05 pad.1@-435.98,-642.05 ; pad.1@-410,-70 -611.1,-70 -637.79,-43.31 -637.79,51.18 -608.98,80 40,80 pad.1@50,70 ; -125,-110 pad.1@-60,-110 ; pad.1@-82.05,-995.98 -82.05,-952.05 pad.1@-70,-940 ; -65,-1244.25 0,-1244.25 65,-1244.25 ; pad.1@-60,-10 50,-10 pad.1@160,-10 ; pad.1@15.98,-642.05 67.95,-642.05 pad.1@70,-640 ; pad.1@50,-110 115,-110 ; 212.05,-421.89 pad.1@212.05,-481.42 ; 271.57,-481.42 pad.1@212.05,-481.42 ; 319.45,-422.5 pad.1@319.45,-350 ; 319.45,-277.5 pad.1@319.45,-350 ; 770,-840 pad.1@770,-920 ; 770,-400 pad.1@770,-320 ; 770,-240 pad.1@770,-320 ; 850,-920 pad.1@770,-920 ; 850,-320 pad.1@770,-320 ; pad.1@1074.8,-816.55 873.45,-816.55 pad.1@770,-920 ; pad.1@1094.49,-102.36 930,-102.36 927.64,-100 850,-100 ; pad.1@212.05,-481.42 298.03,-481.42 319.45,-460 pad.1@319.45,-350 ; pad.1@319.45,-350 319.45,-74.25 338.58,-55.12 496.06,-55.12 509.74,-68.79 632.22,-68.79 678.86,-22.15 793.81,-22.15 850,-78.35 850,-100 ; pad.1@770,-320 850,-240 850,-100 ; -1202.37,-365.71 -1195.6,-365.71 -1173.28,-388.03 -1163.03,-398.28 -761.56,-398.28 -700.4,-459.44 -634.37,-459.44 -634.37,-500.43 -720.07,-500.43 -814.56,-405.94 -1195,-405.94 -1195,-373.08 -1202.37,-365.71 ; -504.37,-500.43 -504.37,-459.44 -412.77,-459.44 -387.52,-484.69 -434.18,-484.69 -449.93,-500.43 -504.37,-500.43 ; pad.1@-504.37,-389.44 -504.37,-388.97 -496.3,-388.97 -495.6,-388.27 -494.44,-389.44 pad.1@-504.37,-389.44 ; pad.1@-504.37,-363.97 -504.37,-355 -499.12,-355 -499.12,-363.97 pad.1@-504.37,-363.97 ; -472.27,-68.59 -452.9,-49.23 -452.9,-24.21 -311.6,-24.21 -291.16,-3.77 -285,-3.77 -285,-57.24 -246.92,-95.31 -193.08,-95.31 -185.34,-87.58 -125,-87.58 -125,-125.31 -254.21,-125.31 -254.21,-103.41 -280.57,-77.05 -289.03,-77.05 -289.03,-66.3 -315.39,-39.94 -352.67,-39.94 -362.67,-49.94 -368.12,-49.94 -386.78,-68.59 -397.5,-68.59 -397.5,-64.82 -404.82,-57.5 -415.18,-57.5 -422.5,-64.82 -422.5,-68.59 -472.27,-68.59 ; -155,-17.58 -155,-3.77 -71.45,-3.77 -72.5,-4.82 -72.5,-15.18 -70.1,-17.58 -155,-17.58 ; -97.78,-1259.84 -93.64,-1255.7 -93.64,-1235 -75.5,-1235 -65,-1224.5 -65,-1259.84 -97.78,-1259.84 ; pad.1@-49.9,-17.58 -47.5,-15.18 -47.5,-4.82 -48.55,-3.77 38.55,-3.77 37.5,-4.82 37.5,-15.18 39.9,-17.58 pad.1@-49.9,-17.58 ; 41.92,-1194.25 55.51,-1180.67 72.12,-1180.67 108.87,-1217.42 345.66,-1217.42 419.73,-1143.35 436.37,-1143.35 438.02,-1145 423.08,-1145 385,-1183.08 385,-1225.5 350.66,-1259.84 65,-1259.84 65,-1217.33 41.92,-1194.25 ; pad.1@60.1,-17.58 62.5,-15.18 62.5,-4.82 61.45,-3.77 148.55,-3.77 147.5,-4.82 147.5,-15.18 149.9,-17.58 pad.1@60.1,-17.58 ; pad.1@81.26,-646.42 82.5,-645.18 82.5,-635 122.53,-635 111.11,-646.42 pad.1@81.26,-646.42 ; 91.92,-160 115,-136.92 115,-87.58 159.63,-87.58 185,-112.95 185,-171.36 175,-181.36 175,-218.64 181.36,-225 115,-225 115,-183.08 91.92,-160 ; 143.68,-464.96 143.68,-446.07 153.03,-436.72 153.03,-415 264.5,-415 270.95,-408.55 270.95,-422.5 415,-422.5 415,-428.64 425.77,-439.41 408.43,-456.76 408.43,-495 271.57,-495 271.57,-456.76 236.7,-421.89 187.39,-421.89 152.52,-456.76 152.52,-473.8 143.68,-464.96 ; pad.1@170.1,-17.58 172.5,-15.18 172.5,-4.82 171.45,-3.77 236.73,-3.77 225.25,-15.25 215,-25.5 215,-43.95 188.62,-17.58 pad.1@170.1,-17.58 ; 305,-277.5 305,-74.5 313,-66.5 316,-66.5 316,-194.15 370,-194.15 370,-216.36 365,-221.36 365,-258.64 370,-263.64 370,-277.5 305,-277.5 ; 504,-81.65 504,-66.5 510.09,-66.5 542.09,-34.5 542.09,11.81 964.57,11.81 964.57,-467.36 743.14,-467.36 740,-470.5 723.98,-454.48 723.98,-387.11 736.86,-400 803.14,-400 850,-353.14 850,-286.86 803.14,-240 736.86,-240 723.98,-252.89 723.98,-215.52 739.5,-200 803.14,-200 850,-153.14 850,-86.86 803.14,-40 736.86,-40 690,-86.86 690,-150.5 653.98,-186.53 653.98,-483.47 705,-534.5 705,-543.44 680.99,-543.44 665,-559.43 665,-533.08 626.92,-495 585,-495 585,-198.64 595,-188.64 595,-161.65 618.01,-161.65 621.36,-165 658.64,-165 685,-138.64 685,-101.36 658.64,-75 621.36,-75 614.71,-81.65 504,-81.65 ; 725,-851.86 725,-788.14 736.86,-800 803.14,-800 850,-753.14 850,-686.86 803.14,-640 769.5,-640 775,-634.5 775,-537.36 935,-537.36 935,-586.92 964.57,-616.49 964.57,-631.74 884.44,-551.62 859.35,-551.62 849.35,-541.62 812.07,-541.62 785.71,-567.97 785.71,-605.25 812.07,-631.61 849.35,-631.61 857.4,-623.57 918.73,-684.9 918.73,-723.73 908.73,-733.73 908.73,-771.01 935.09,-797.37 964.57,-797.37 964.57,-896.29 958.03,-889.75 920.75,-889.75 894.39,-916.11 894.39,-920.01 861.12,-953.27 849.86,-953.27 850,-953.14 850,-886.86 803.14,-840 736.86,-840 725,-851.86
  Bottom Layer w10: pad.1@-1420,-290 -1280,-290 -1260,-310 -1260,-400 -1275,-400 -1310,-435 -1310,-440 -1300,-450 -1300,-500 -1380,-500 -1400,-520 pad.1@-1400,-600 ; -569.37,-538.94 pad.1@-569.37,-473.94 ; -504.37,-473.94 pad.1@-569.37,-473.94 ; pad.1@-501.47,-376.47 -501.47,-440.99 -534.37,-473.89 pad.1@-569.37,-473.94 ; pad.1@-490,-910 -490,-650 -529.37,-650 -569.37,-610 pad.1@-569.37,-473.94 ; pad.1@-410,-70 -410,-412.46 ; pad.1@-70,-940 -10,-940 0,-940 20,-920 ; -60,-45 -60,-110 pad.1@-60,-10 ; pad.1@0,-1244.25 50,-1194.25 50,-950 20,-920 ; 50,-45 50,-110 50,-10 pad.1@50,70 ; pad.1@160,-10 160,-450 140,-470 ; 212.05,-540.94 pad.1@212.05,-481.42 ; 212.05,-421.89 pad.1@212.05,-481.42 ; 690,-320 770,-320 770,-400 ; 770,-840 770,-920 850,-920 ; 935,-560 pad.1@1000,-560 ; pad.1@1107.09,137.8 1107.09,0 1094.49,-12.6 1094.49,-102.36 1096.81,-100.05 1169.27,-100.05 1208.37,-139.14 1208.37,-538.32 1208.37,-543.6 1141.73,-610.24 1050.24,-610.24 pad.1@1000,-560 ; pad.1@1207.09,-1389.76 1207.09,-892.13 1131.51,-816.55 1074.8,-816.55 1000,-741.75 pad.1@1000,-560 ; pad.1@-569.37,-473.94 -430,-473.94 ; -430,-473.94 -424.88,-468.82 ; -430,-473.94 -424.88,-468.82 ; -424.88,-468.82 -410,-453.94 ; -424.88,-468.82 -410,-453.94 ; -410,-453.94 -410,-425.2 ; -410,-453.94 -410,-425.2 ; -410,-425.2 -410,-412.46 ; -410,-425.2 -410,-412.46 ; 20,-920 20,-660 40,-640 70,-640 70,-473.31 86.61,-456.69 126.69,-456.69 140,-470 ; 140,-470 140,-530 160,-550 190,-550 212.05,-527.95 pad.1@212.05,-481.42 ; -598.86,-710.5 -598.86,-536.37 -596.29,-538.94 -542.45,-538.94 -504.37,-500.86 -504.37,-447.01 -527.45,-423.94 -504.37,-400.86 -504.37,-388.97 -496.3,-388.97 -495.6,-388.27 -472.76,-411.12 -435.48,-411.12 -415,-390.64 -415,-731.36 -425,-741.36 -425,-778.64 -398.64,-805 -385.65,-805 -385.65,-853.39 -374.03,-865 -398.64,-865 -425,-891.36 -425,-904.06 -478.27,-904.06 -484.82,-897.5 -495.18,-897.5 -496.53,-898.85 -582.67,-812.72 -556.16,-812.72 -529.8,-786.36 -529.8,-749.08 -556.16,-722.72 -577.66,-722.72 -598.86,-710.5 ; -534.37,-317.01 -534.37,-57.76 -516.54,-75.59 -502.4,-75.59 -489.12,-88.87 -489.12,-337.48 -499.12,-347.48 -499.12,-363.97 -504.37,-363.97 -504.37,-347.01 -534.37,-317.01 ; pad.1@-502.5,-655.18 -495.18,-662.5 -484.82,-662.5 -477.5,-655.18 -477.5,-644.82 -484.82,-637.5 -495.18,-637.5 -502.5,-644.82 pad.1@-502.5,-655.18 ; -104.21,-1207.85 -85,-1188.64 -85,-1154.18 -65,-1134.18 -65,-955.5 -68,-952.5 -64.82,-952.5 -57.5,-945.18 -57.5,-934.82 -64.82,-927.5 -75.18,-927.5 -82.5,-934.82 -82.5,-938 -85,-935.5 -85,-921.36 -103.43,-902.93 -95.47,-894.97 -92.39,-898.06 -85.9,-898.06 -75.9,-908.06 -38.62,-908.06 -12.26,-881.69 -12.26,-845 -1.57,-845 4.41,-839.03 4.41,-848.21 4.41,-862.71 24.95,-883.25 24.95,-897.39 39.03,-911.47 35,-915.5 35,-1087.33 26.92,-1079.25 -26.92,-1079.25 -65,-1117.33 -65,-1159.75 -85,-1179.75 -85,-1241.21 -93.64,-1232.57 -93.64,-1218.42 -104.21,-1207.85 ; -90.98,-49.06 -90.98,11.81 -31.06,11.81 -31.06,-47.01 -33.08,-45 -86.92,-45 -90.98,-49.06 ; pad.1@-72.5,-15.18 -65.18,-22.5 -54.82,-22.5 -47.5,-15.18 -47.5,-4.82 -54.82,2.5 -65.18,2.5 -72.5,-4.82 pad.1@-72.5,-15.18 ; 38.94,-747.55 38.94,-335 68.64,-335 73.03,-330.61 73.03,-389.44 63.03,-399.44 63.03,-436.72 82.48,-456.16 63.68,-474.96 63.68,-512.24 73.68,-522.24 73.68,-627.5 64.82,-627.5 57.5,-634.82 57.5,-645.18 64.82,-652.5 73.68,-652.5 73.68,-712.81 38.94,-747.55 ; 38.94,-45 38.94,-16.61 44.82,-22.5 55.18,-22.5 62.5,-15.18 62.5,-4.82 55.18,2.5 44.82,2.5 38.94,-3.39 38.94,11.81 69.12,11.81 69.12,-38.18 69.12,-45 38.94,-45 ; 134.23,-455.51 153.03,-436.72 153.03,-399.44 143.03,-389.44 143.03,-301.96 148.89,-296.1 148.89,-324.85 175.25,-351.21 212.53,-351.21 225,-338.75 225,-421.89 187.39,-421.89 152.52,-456.76 152.52,-473.8 134.23,-455.51 ; 139.12,-23.69 139.12,11.81 168.94,11.81 168.94,-1.26 165.18,2.5 154.82,2.5 147.5,-4.82 147.5,-15.18 154.82,-22.5 165.18,-22.5 168.94,-18.74 168.94,-49.28 157.05,-61.17 157.05,-41.61 139.12,-23.69 ; 143.68,-706.82 143.68,-522.24 153.68,-512.24 153.68,-507.23 187.39,-540.94 225,-540.94 225,-596.13 222.08,-599.06 187.39,-599.06 152.52,-633.93 152.52,-683.24 164.28,-695 155.5,-695 143.68,-706.82 ; 514.5,-405 575,-344.5 575,-294.5 594.5,-275 701.86,-275 690,-286.86 690,-353.14 736.86,-400 803.14,-400 845,-358.14 845,-394.5 850.5,-400 845,-405.5 845,-541.62 812.07,-541.62 800.25,-553.44 728.27,-553.44 718.27,-543.44 695,-543.44 695,-445.5 654.5,-405 514.5,-405 ; 695,-881.86 695,-758.14 736.86,-800 803.14,-800 848.14,-755 865,-755 865,-953.27 849.86,-953.27 850,-953.14 850,-886.86 803.14,-840 736.86,-840 695,-881.86 ; 915,-685.5 915,-435 968.5,-435 968.5,-499.57 935,-533.08 935,-586.92 968.5,-620.43 968.5,-707.37 935.09,-707.37 935,-707.46 935,-705.5 915,-685.5
  Bottom Layer w20: pad.1@1107.09,137.8 pad.1@1207.09,137.8
$Net66: pad.1@-121.42,-544.02 pad.1@-1300,-199.69 pad.1@-1420,-190 | length 1635
  Top Layer w10: pad.1@-1420,-190 -1369.68,-190 -1360,-199.69 -1300,-199.69 -141.73,-199.69 -121.42,-220 pad.1@-121.42,-544.02
$Net67: pad.1@15.98,-917.64
$Net68: pad.1@15.98,-897.95
copper on no net: | length 18472.4
  Top Layer w8: -1578.74,-1492.13 -1578.74,244.09 1303.15,244.09 1303.15,-1492.13 -1578.74,-1492.13
  Bottom Layer w8: -1578.74,-1492.13 -1578.74,244.09 1303.15,244.09 1303.15,-1492.13 -1578.74,-1492.13

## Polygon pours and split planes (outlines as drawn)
$Net65 on Bottom Layer "Bottom Layer-$Net65" (solid, pour order 26): 4.41,-848.21 4.41,-862.71 24.95,-883.25 24.95,-897.39 39.03,-911.47 35,-915.5 35,-1087.33 26.92,-1079.25 -26.92,-1079.25 -65,-1117.33 -65,-1159.75 -85,-1179.75 -85,-1241.21 -93.64,-1232.57 -93.64,-1218.42 -104.21,-1207.85 -85,-1188.64 -85,-1154.18 -65,-1134.18 -65,-955.5 -68,-952.5 -64.82,-952.5 -57.5,-945.18 -57.5,-934.82 -64.82,-927.5 -75.18,-927.5 -82.5,-934.82 -82.5,-938 -85,-935.5 -85,-921.36 -103.43,-902.93 -95.47,-894.97 -92.39,-898.06 -85.9,-898.06 -75.9,-908.06 -38.62,-908.06 -12.26,-881.69 -12.26,-845 -1.57,-845 4.41,-839.03
$Net65 on Bottom Layer "Bottom Layer-$Net65 1" (solid, pour order 24): 865,-953.27 849.86,-953.27 850,-953.14 850,-886.86 803.14,-840 736.86,-840 695,-881.86 695,-758.14 736.86,-800 803.14,-800 848.14,-755 865,-755
$Net65 on Bottom Layer "Bottom Layer-$Net65 2" (solid, pour order 22): 73.03,-389.44 63.03,-399.44 63.03,-436.72 82.48,-456.16 63.68,-474.96 63.68,-512.24 73.68,-522.24 73.68,-627.5 64.82,-627.5 57.5,-634.82 57.5,-645.18 64.82,-652.5 73.68,-652.5 73.68,-712.81 38.94,-747.55 38.94,-335 68.64,-335 73.03,-330.61
$Net65 on Bottom Layer "Bottom Layer-$Net65 3" (solid, pour order 20): 187.39,-540.94 225,-540.94 225,-596.13 222.08,-599.06 187.39,-599.06 152.52,-633.93 152.52,-683.24 164.28,-695 155.5,-695 143.68,-706.82 143.68,-522.24 153.68,-512.24 153.68,-507.23
$Net65 on Bottom Layer "Bottom Layer-$Net65 4" (solid, pour order 18): 690,-286.86 690,-353.14 736.86,-400 803.14,-400 845,-358.14 845,-394.5 850.5,-400 845,-405.5 845,-541.62 812.07,-541.62 800.25,-553.44 728.27,-553.44 718.27,-543.44 695,-543.44 695,-445.5 654.5,-405 514.5,-405 575,-344.5 575,-294.5 594.5,-275 701.86,-275
no net on Bottom Layer "Bottom Layer-No Net" (solid, pour order 16): -502.5,-655.18 -502.5,-644.82 -495.18,-637.5 -484.82,-637.5 -477.5,-644.82 -477.5,-655.18 -484.82,-662.5 -495.18,-662.5
$Net65 on Bottom Layer "Bottom Layer-$Net65 5" (solid, pour order 14): -472.76,-411.12 -435.48,-411.12 -415,-390.64 -415,-731.36 -425,-741.36 -425,-778.64 -398.64,-805 -385.65,-805 -385.65,-853.39 -374.03,-865 -398.64,-865 -425,-891.36 -425,-904.06 -478.27,-904.06 -484.82,-897.5 -495.18,-897.5 -496.53,-898.85 -582.67,-812.72 -556.16,-812.72 -529.8,-786.36 -529.8,-749.08 -556.16,-722.72 -577.66,-722.72 -598.86,-710.5 -598.86,-536.37 -596.29,-538.94 -542.45,-538.94 -504.37,-500.86 -504.37,-447.01 -527.45,-423.94 -504.37,-400.86 -504.37,-388.97 -496.3,-388.97 -495.6,-388.27
$Net65 on Bottom Layer "Bottom Layer-$Net65 6" (solid, pour order 12): 148.89,-324.85 175.25,-351.21 212.53,-351.21 225,-338.75 225,-421.89 187.39,-421.89 152.52,-456.76 152.52,-473.8 134.23,-455.51 153.03,-436.72 153.03,-399.44 143.03,-389.44 143.03,-301.96 148.89,-296.1
$Net65 on Bottom Layer "Bottom Layer-$Net65 7" (solid, pour order 10): -516.54,-75.59 -502.4,-75.59 -489.12,-88.87 -489.12,-337.48 -499.12,-347.48 -499.12,-363.97 -504.37,-363.97 -504.37,-347.01 -534.37,-317.01 -534.37,-57.76
$Net65 on Bottom Layer "Bottom Layer-$Net65 8" (solid, pour order 8): 968.5,-499.57 935,-533.08 935,-586.92 968.5,-620.43 968.5,-707.37 935.09,-707.37 935,-707.46 935,-705.5 915,-685.5 915,-435 968.5,-435
no net on Bottom Layer "Bottom Layer-No Net 1" (solid, pour order 6): -72.5,-15.18 -72.5,-4.82 -65.18,2.5 -54.82,2.5 -47.5,-4.82 -47.5,-15.18 -54.82,-22.5 -65.18,-22.5
$Net65 on Bottom Layer "Bottom Layer-$Net65 9" (solid, pour order 4): -31.06,-47.01 -33.08,-45 -86.92,-45 -90.98,-49.06 -90.98,11.81 -31.06,11.81
$Net65 on Bottom Layer "Bottom Layer-$Net65 10" (solid, pour order 2): 69.12,-38.18 69.12,-45 38.94,-45 38.94,-16.61 44.82,-22.5 55.18,-22.5 62.5,-15.18 62.5,-4.82 55.18,2.5 44.82,2.5 38.94,-3.39 38.94,11.81 69.12,11.81
$Net65 on Bottom Layer "Bottom Layer-$Net65 11" (solid, pour order 0): 168.94,-1.26 165.18,2.5 154.82,2.5 147.5,-4.82 147.5,-15.18 154.82,-22.5 165.18,-22.5 168.94,-18.74 168.94,-49.28 157.05,-61.17 157.05,-41.61 139.12,-23.69 139.12,11.81 168.94,11.81
$Net65 on Top Layer "Top Layer-$Net65" (solid, pour order 60): -65,-1259.84 -97.78,-1259.84 -93.64,-1255.7 -93.64,-1235 -75.5,-1235 -65,-1224.5
$Net65 on Top Layer "Top Layer-$Net65 1" (solid, pour order 58): 438.02,-1145 423.08,-1145 385,-1183.08 385,-1225.5 350.66,-1259.84 65,-1259.84 65,-1217.33 41.92,-1194.25 55.51,-1180.67 72.12,-1180.67 108.87,-1217.42 345.66,-1217.42 419.73,-1143.35 436.37,-1143.35
$Net65 on Top Layer "Top Layer-$Net65 2" (solid, pour order 56): 111.11,-646.42 81.26,-646.42 82.5,-645.18 82.5,-635 122.53,-635
$Net65 on Top Layer "Top Layer-$Net65 3" (solid, pour order 54): -1173.28,-388.03 -1163.03,-398.28 -761.56,-398.28 -700.4,-459.44 -634.37,-459.44 -634.37,-500.43 -720.07,-500.43 -814.56,-405.94 -1195,-405.94 -1195,-373.08 -1202.37,-365.71 -1195.6,-365.71
$Net65 on Top Layer "Top Layer-$Net65 4" (solid, pour order 52): -387.52,-484.69 -434.18,-484.69 -449.93,-500.43 -504.37,-500.43 -504.37,-459.44 -412.77,-459.44
$Net65 on Top Layer "Top Layer-$Net65 5" (solid, pour order 50): 270.95,-422.5 415,-422.5 415,-428.64 425.77,-439.41 408.43,-456.76 408.43,-495 271.57,-495 271.57,-456.76 236.7,-421.89 187.39,-421.89 152.52,-456.76 152.52,-473.8 143.68,-464.96 143.68,-446.07 153.03,-436.72 153.03,-415 264.5,-415 270.95,-408.55
$Net65 on Top Layer "Top Layer-$Net65 6" (solid, pour order 48): -494.44,-389.44 -504.37,-389.44 -504.37,-388.97 -496.3,-388.97 -495.6,-388.27
$Net65 on Top Layer "Top Layer-$Net65 7" (solid, pour order 46): -499.12,-363.97 -504.37,-363.97 -504.37,-355 -499.12,-355
$Net65 on Top Layer "Top Layer-$Net65 8" (solid, pour order 44): 316,-194.15 370,-194.15 370,-216.36 365,-221.36 365,-258.64 370,-263.64 370,-277.5 305,-277.5 305,-74.5 313,-66.5 316,-66.5
$Net65 on Top Layer "Top Layer-$Net65 9" (solid, pour order 42): 185,-112.95 185,-171.36 175,-181.36 175,-218.64 181.36,-225 115,-225 115,-183.08 91.92,-160 115,-136.92 115,-87.58 159.63,-87.58
$Net65 on Top Layer "Top Layer-$Net65 10" (solid, pour order 40): -285,-57.24 -246.92,-95.31 -193.08,-95.31 -185.34,-87.58 -125,-87.58 -125,-125.31 -254.21,-125.31 -254.21,-103.41 -280.57,-77.05 -289.03,-77.05 -289.03,-66.3 -315.39,-39.94 -352.67,-39.94 -362.67,-49.94 -368.12,-49.94 -386.78,-68.59 -397.5,-68.59 -397.5,-64.82 -404.82,-57.5 -415.18,-57.5 -422.5,-64.82 -422.5,-68.59 -472.27,-68.59 -452.9,-49.23 -452.9,-24.21 -311.6,-24.21 -291.16,-3.77 -285,-3.77
$Net65 on Top Layer "Top Layer-$Net65 11" (solid, pour order 38): 225.25,-15.25 215,-25.5 215,-43.95 188.62,-17.58 170.1,-17.58 172.5,-15.18 172.5,-4.82 171.45,-3.77 236.73,-3.77
$Net65 on Top Layer "Top Layer-$Net65 12" (solid, pour order 36): -72.5,-4.82 -72.5,-15.18 -70.1,-17.58 -155,-17.58 -155,-3.77 -71.45,-3.77
$Net65 on Top Layer "Top Layer-$Net65 13" (solid, pour order 34): 37.5,-4.82 37.5,-15.18 39.9,-17.58 -49.9,-17.58 -47.5,-15.18 -47.5,-4.82 -48.55,-3.77 38.55,-3.77
$Net65 on Top Layer "Top Layer-$Net65 14" (solid, pour order 32): 147.5,-4.82 147.5,-15.18 149.9,-17.58 60.1,-17.58 62.5,-15.18 62.5,-4.82 61.45,-3.77 148.55,-3.77
$Net65 on Top Layer "Top Layer-$Net65 15" (solid, pour order 30): 935,-586.92 964.57,-616.49 964.57,-631.74 884.44,-551.62 859.35,-551.62 849.35,-541.62 812.07,-541.62 785.71,-567.97 785.71,-605.25 812.07,-631.61 849.35,-631.61 857.4,-623.57 918.73,-684.9 918.73,-723.73 908.73,-733.73 908.73,-771.01 935.09,-797.37 964.57,-797.37 964.57,-896.29 958.03,-889.75 920.75,-889.75 894.39,-916.11 894.39,-920.01 861.12,-953.27 849.86,-953.27 850,-953.14 850,-886.86 803.14,-840 736.86,-840 725,-851.86 725,-788.14 736.86,-800 803.14,-800 850,-753.14 850,-686.86 803.14,-640 769.5,-640 775,-634.5 775,-537.36 935,-537.36
$Net65 on Top Layer "Top Layer-$Net65 16" (solid, pour order 28): 964.57,-467.36 743.14,-467.36 740,-470.5 723.98,-454.48 723.98,-387.11 736.86,-400 803.14,-400 850,-353.14 850,-286.86 803.14,-240 736.86,-240 723.98,-252.89 723.98,-215.52 739.5,-200 803.14,-200 850,-153.14 850,-86.86 803.14,-40 736.86,-40 690,-86.86 690,-150.5 653.98,-186.53 653.98,-483.47 705,-534.5 705,-543.44 680.99,-543.44 665,-559.43 665,-533.08 626.92,-495 585,-495 585,-198.64 595,-188.64 595,-161.65 618.01,-161.65 621.36,-165 658.64,-165 685,-138.64 685,-101.36 658.64,-75 621.36,-75 614.71,-81.65 504,-81.65 504,-66.5 510.09,-66.5 542.09,-34.5 542.09,11.81 964.57,11.81

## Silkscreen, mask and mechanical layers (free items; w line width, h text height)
Top Overlay:
  drawing of 842 lines, arcs and shapes, not listed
